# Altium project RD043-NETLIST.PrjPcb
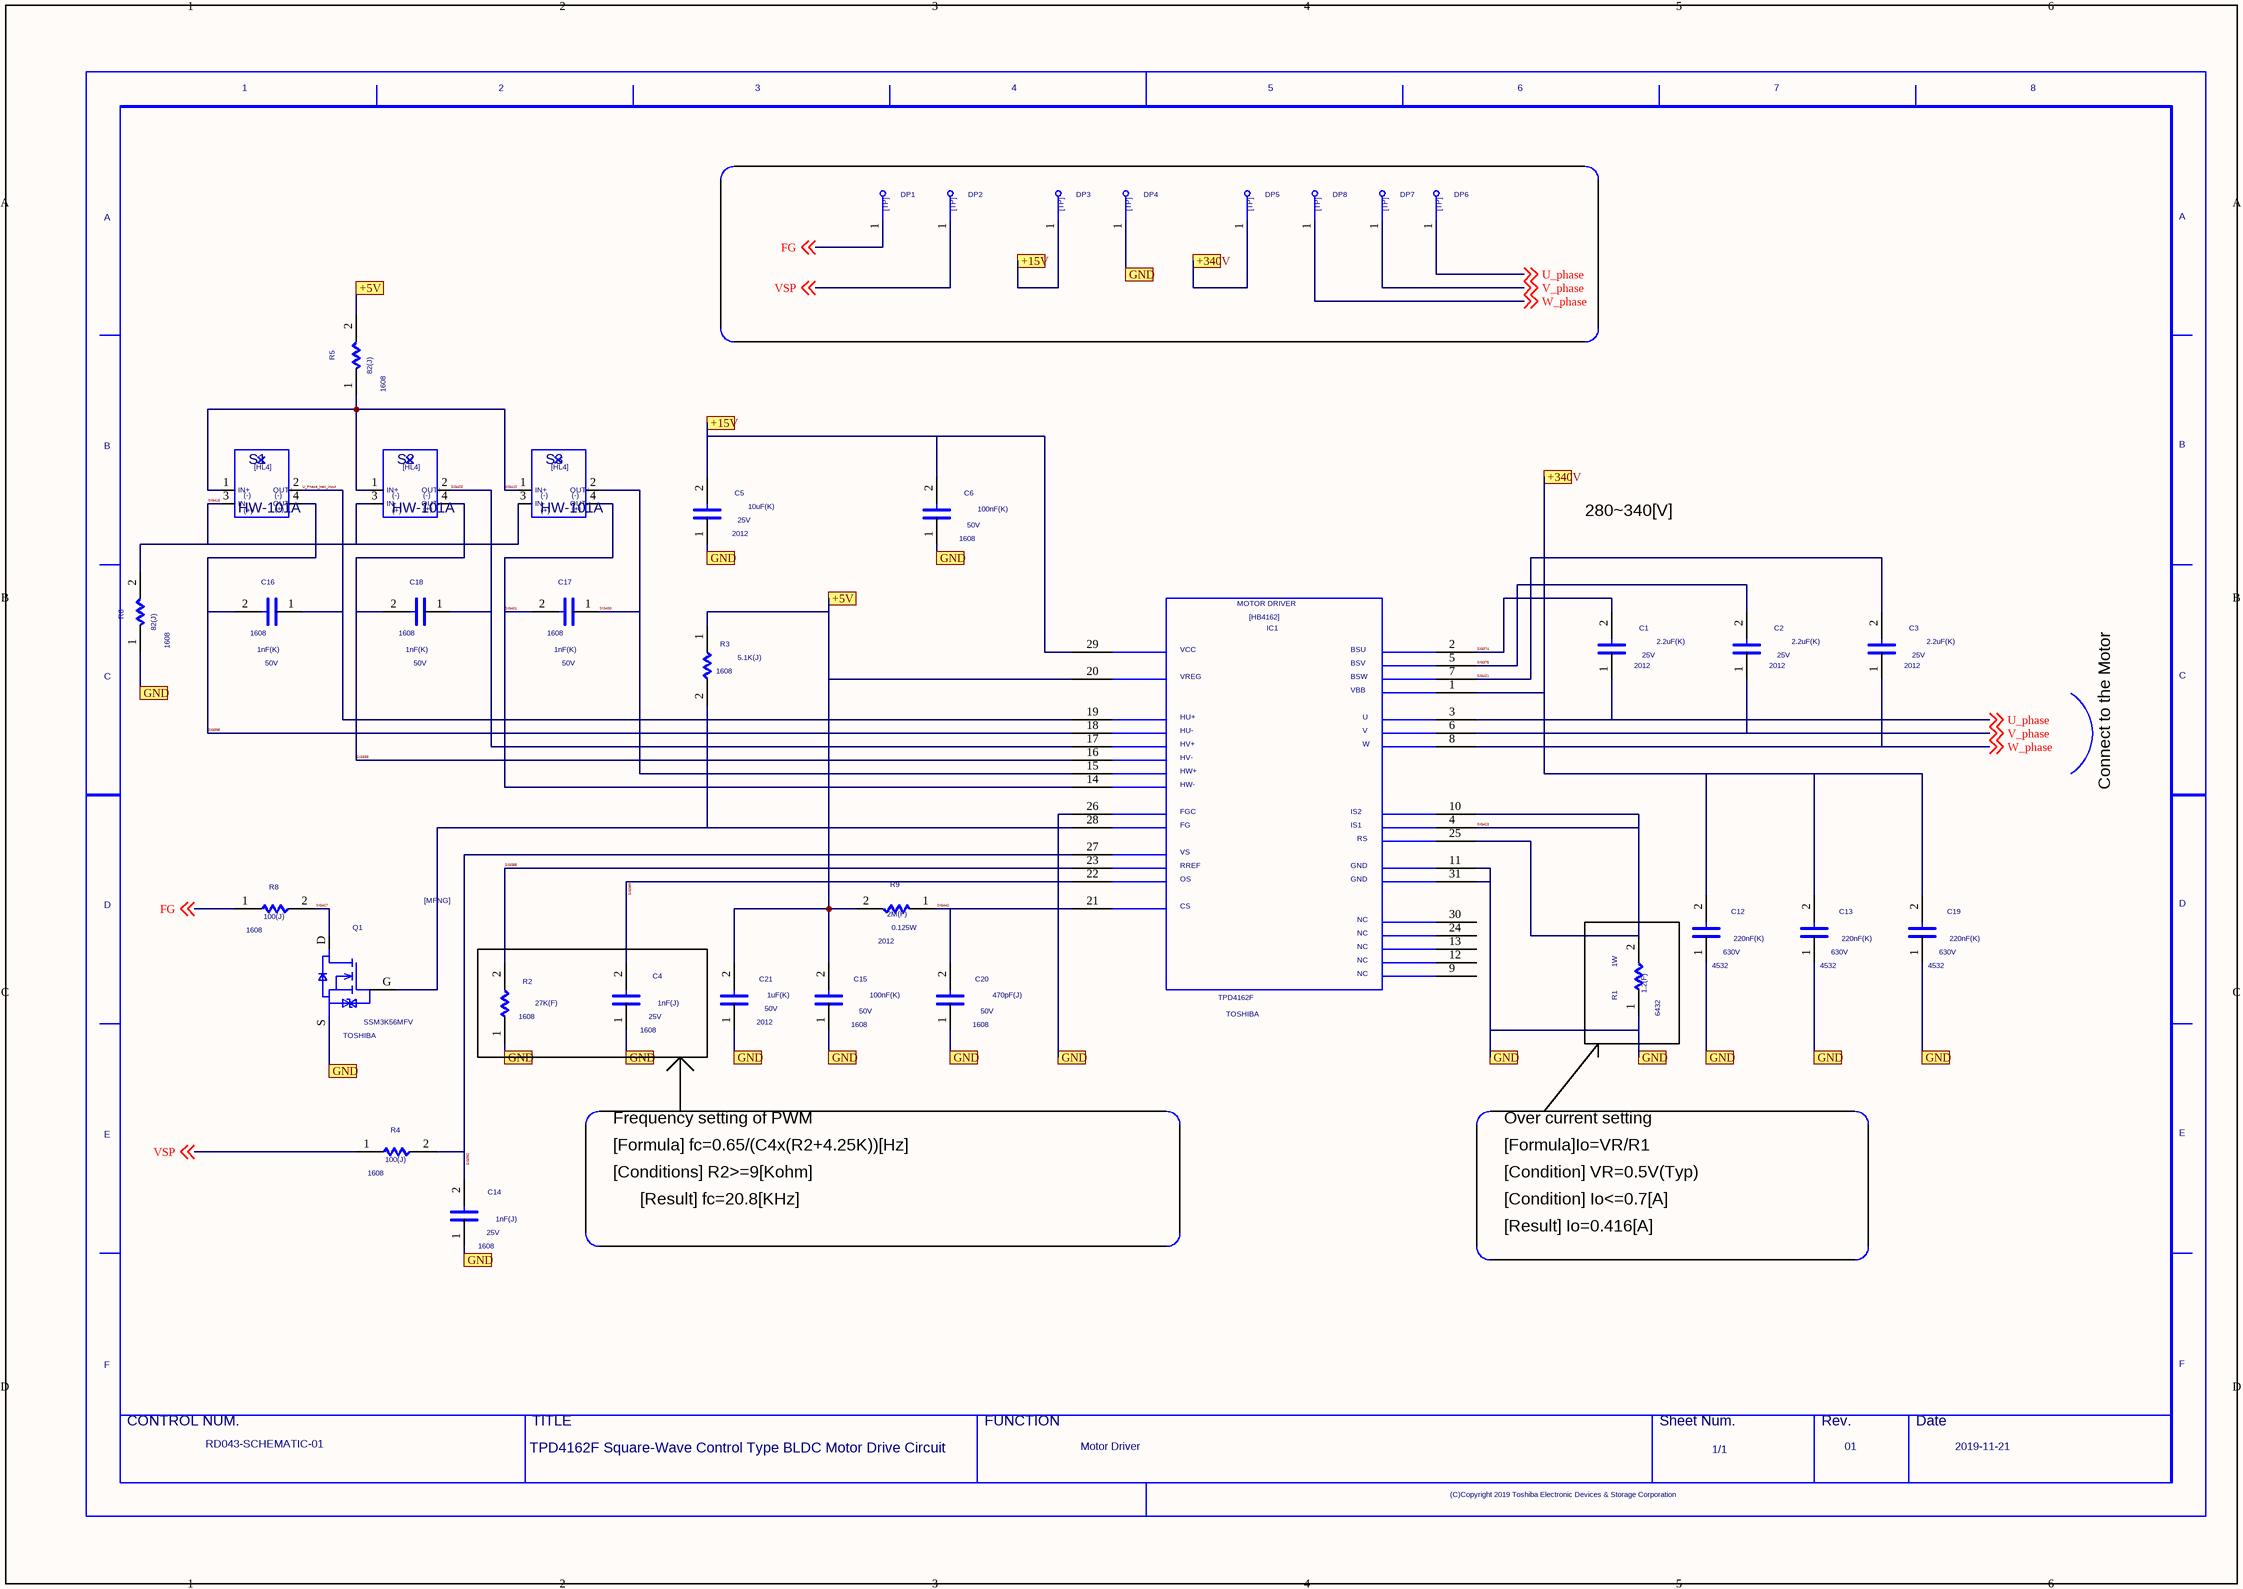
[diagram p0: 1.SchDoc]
1 sheet, 38 parts. Net scope: flat (ports and power ports of the same name join across sheets).

## Sheet 1.SchDoc
size 420 x 297 mm

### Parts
C1  SIZECODESMD: 2012  VAL2: 25V  VAL1: 2.2uF(K)  (hidden comment: C)
C2  SIZECODESMD: 2012  VAL2: 25V  VAL1: 2.2uF(K)  (hidden comment: C)
C3  SIZECODESMD: 2012  VAL2: 25V  VAL1: 2.2uF(K)  (hidden comment: C)
C4  SIZECODESMD: 1608  VAL2: 25V  VAL1: 1nF(J)  (hidden comment: C)
C5  SIZECODESMD: 2012  VAL2: 25V  VAL1: 10uF(K)  (hidden comment: C)
C6  SIZECODESMD: 1608  VAL2: 50V  VAL1: 100nF(K)  (hidden comment: C)
C12  SIZECODESMD: 4532  VAL2: 630V  VAL1: 220nF(K)  (hidden comment: C)
C13  SIZECODESMD: 4532  VAL2: 630V  VAL1: 220nF(K)  (hidden comment: C)
C14  SIZECODESMD: 1608  VAL2: 25V  VAL1: 1nF(J)  (hidden comment: C)
C15  SIZECODESMD: 1608  VAL2: 50V  VAL1: 100nF(K)  (hidden comment: C)
C16  SIZECODESMD: 1608  VAL2: 50V  VAL1: 1nF(K)  (hidden comment: C)
C17  SIZECODESMD: 1608  VAL2: 50V  VAL1: 1nF(K)  (hidden comment: C)
C18  SIZECODESMD: 1608  VAL2: 50V  VAL1: 1nF(K)  (hidden comment: C)
C19  SIZECODESMD: 4532  VAL2: 630V  VAL1: 220nF(K)  (hidden comment: C)
C20  SIZECODESMD: 1608  VAL2: 50V  VAL1: 470pF(J)  (hidden comment: C)
C21  SIZECODESMD: 2012  VAL2: 50V  VAL1: 1uF(K)  (hidden comment: C)
DP1  TP  (value not drawn)
DP2  TP  (value not drawn)
DP3  TP  (value not drawn)
DP4  TP  (value not drawn)
DP5  TP  (value not drawn)
DP6  TP  (value not drawn)
DP7  TP  (value not drawn)
DP8  TP  (value not drawn)
IC1  USERCOMPTEXT3: TOSHIBA  VAL3: TPD4162F  (hidden comment: HB4162)
Q1  USERCOMPTEXT1: TOSHIBA  VAL1: SSM3K56MFV  (hidden comment: MFNG)
R1  SIZECODESMD: 6432  VAL2: 1W  VAL1: 1.2(F)  (hidden comment: R)
R2  SIZECODESMD: 1608  VAL1: 27K(F)  (hidden comment: R)
R3  SIZECODESMD: 1608  VAL1: 5.1K(J)  (hidden comment: R)
R4  SIZECODESMD: 1608  VAL1: 100(J)  (hidden comment: R)
R5  SIZECODESMD: 1608  VAL1: 82(J)  (hidden comment: R)
R6  SIZECODESMD: 1608  VAL1: 82(J)  (hidden comment: R)
R8  SIZECODESMD: 1608  VAL1: 100(J)  (hidden comment: R)
R9  SIZECODESMD: 2012  VAL2: 0.125W  VAL1: 2M(F)  (hidden comment: R)
S1  VAL3: HW-101A  (hidden comment: HL4)
S2  VAL3: HW-101A  (hidden comment: HL4)
S3  VAL3: HW-101A  (hidden comment: HL4)
U?  DATE: 2019-11-21  TITLE: TPD4162F Square-Wave Control Type / BLDC Motor Drive Circuit  REVISION: 01  SHEETNUMBER: 1/1  DRAWINGNUMBER: RD043-SCHEMATIC-01  FUNCTION: Motor Driver  (hidden comment: WAKU_DEF100)

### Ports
+5V, +15V, +340V, GND

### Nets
FG: DP1.1 R8.1 ; off-sheet FG
Rotation_information: IC1.28 Q1.G R3.2
SIG374: C1.2 IC1.2
SIG375: C2.2 IC1.5
SIG388: IC1.23 R2.2
SIG389: C4.2 IC1.22
SIG392: C14.2 IC1.27 R4.2
SIG398: C16.2 IC1.18 S1.4
SIG399: C18.2 IC1.16 S2.4
SIG400: C17.1 IC1.15 S3.2
SIG401: C17.2 IC1.14 S3.4
SIG402: C18.1 IC1.17 S2.2
SIG410: R5.1 S1.1 S2.1 S3.1
SIG415: R6.2 S1.3 S2.3 S3.3
SIG421: C3.2 IC1.7
SIG423: IC1.4 IC1.10 IC1.25 R1.2
SIG427: Q1.D R8.2
SIG440: C20.2 IC1.21 R9.1
U_phase: C1.1 DP6.1 IC1.3 ; off-sheet U_phase
U_Phase_Hall_Input: C16.1 IC1.19 S1.2
V_phase: C2.1 DP7.1 IC1.6 ; off-sheet V_phase
VSP: DP2.1 R4.1 ; off-sheet VSP
W_phase: C3.1 DP8.1 IC1.8 ; off-sheet W_phase
NetC4_1: C4.1 C5.1 C6.1 C12.1 C13.1 C14.1 C15.1 C19.1 C20.1 C21.1 DP4.1 IC1.11 IC1.26 IC1.31 Q1.S R1.1 R2.1 R6.1 ; port GND
NetC5_2: C5.2 C6.2 DP3.1 IC1.29 ; port +15V
NetC12_2: C12.2 C13.2 C19.2 DP5.1 IC1.1 ; port +340V
NetC15_2: C15.2 C21.2 IC1.20 R3.1 R5.2 R9.2 ; port +5V

Not connected (* = marked no-connect by the designer): IC1 9 12 13 24 30

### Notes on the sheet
- 280~340[V]
- Connect to the Motor
- Frequency setting of PWM
- Over current setting
- [Formula] fc=0.65/(C4x(R2+4.25K))[Hz]
- [Conditions] R2>=9[Kohm]
- [Result] fc=20.8[KHz]
- [Formula]Io=VR/R1
- [Condition] VR=0.5V(Typ)
- [Condition] Io<=0.7[A]
- [Result] Io=0.416[A]

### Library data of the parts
C1-C3 = C: PARTNAME: GDM030002425; OriginalSymbolOrigin: (2540,7620); VAL3: GRM219B31E225KA75D; COMPONENTNAME: GDM030002425_package; MAXGCOUNT: 1
C4 C14 = C: PARTNAME: PRT_3; OriginalSymbolOrigin: (2540,7620); TEMPCHARACTERI2: CH; RATEDVOLTAGE: 25; MAXGCOUNT: 1; OUMEMAKER: MRT 村田製作所; QUADMODEL: CON_1N; FNLEADFREETHET1GT2GMCTH1: N_N_N; OUMECLASSIFICATION: セラミックコンデンサ; NOMINALCAPACITA: 1n; OUMEMAKERKATAMEI: GRM1882C1E102JA01D; CAPACITANCETOLE: J; CDMASTERCADCELG: C8100E; ADSMODELNAME: s_GRM1882C1E102JA01D
C5 = C: PARTNAME: K0302660; OriginalSymbolOrigin: (2540,7620); VAL3: TMK212BBJ106KG-T; COMPONENTNAME: K0302660_package; MAXGCOUNT: 1
C6 C15 = C: PARTNAME: GDM030001707; OriginalSymbolOrigin: (2540,7620); VAL3: GCM188R71H104KA57D; COMPCOMMENT: 代替：C1608JB1H104K; COMPONENTNAME: GDM030001707_package; MAXGCOUNT: 1
C12 C13 C19 = C: PARTNAME: PRT_6; OriginalSymbolOrigin: (2540,7620); MAXGCOUNT: 1; TEMPCHARACTERI2: B; RATEDVOLTAGE: 250; CAPACITANCETOLE: K; NOMINALCAPACITA: 150n; FNLEADFREETHET1GT2GMCTH1: N_N_N; CDMASTERCADCELG: DC835R; OUMEMAKER: TDK ＴＤＫ; OUMEMAKERKATAMEI: C4532JB2E154KT_EMBEDED; OUMECLASSIFICATION: セラミックコンデンサ; ADSMODELNAME: s_C4532JB2E154KT_EMBEDED; QUADMODEL: CON_150N
C16-C18 = C: PARTNAME: GDM030001796; OriginalSymbolOrigin: (2540,7620); VAL3: CM105B102K50AT; COMPONENTNAME: GDM030001796_package; MAXGCOUNT: 1
C20 = C: PARTNAME: GDM030001728; OriginalSymbolOrigin: (2540,7620); VAL3: GCM1885C1H471JA16D; MAXGCOUNT: 1; COMPONENTNAME: GDM030001728_package
C21 = C: PARTNAME: GDM030002107; OriginalSymbolOrigin: (2540,7620); VAL3: GRM21BB31H105KA12L; COMPONENTNAME: GDM030002107_package; MAXGCOUNT: 1
DP1-DP8 = TP: PARTNAME: ZS_DTP805; TIME: 16:12:21; UPDATEUSER: fukuda-y; UPDATETIME: 16:18:11; SAVECOUNT: 2; SAVEAREA0: -242,-92,12810,7836; OriginalSymbolOrigin: (0,7620); COMPONENTNAME: ZS_DTP805_package; MAXGCOUNT: 1
IC1 = HB4162: PARTNAME: K48S0004; OUMEPARTTYPE: IC; SAVEAREA0: -82747,-21522,160014,99323; TIME: 17:23:26; UPDATEUSER: w90028dm; UPDATETIME: 09:08:57; SAVECOUNT: 14; OriginalSymbolOrigin: (7620,76200); COMPONENTNAME: K48S0004_package; MAXGCOUNT: 1
Q1 = MFNG: PARTNAME: K4101030; OUMEPARTTYPE: Q; SAVECOUNT: 17; SAVEAREA0: -7084,-293,21840,15991; OriginalSymbolOrigin: (5080,12700); COMPONENTNAME: K4101030_package; MAXGCOUNT: 1
R1 = R: SQ_PART_MODEL: RES_1K; PARTNAME: PRT_5; OriginalSymbolOrigin: (5080,5080); MAXGCOUNT: 1; RESISTANCETOLER: J; NOMINALRESISTAN: 1K; FNLEADFREETHET1GT2GMCTH1: 3_1_N; CDMASTERCADCELG: R8100A; OUMECLASSIFICATION: 表面実装用固定抵抗器; ADSCNVFLAG: ON
R2 = R: PARTNAME: PRT_2; OriginalSymbolOrigin: (5080,5080); MAXGCOUNT: 1; OUMEMAKER: NAE パナソニックエレクトロニックデバイス; QUADMODEL: RES_27K; MOUNTINGFORMSMD: SMD; FNLEADFREETHET1GT2GMCTH1: N_N_N; OUMECLASSIFICATION: 表面実装用固定抵抗器; RESISTANCETOLER: F; POWERRATING: 100m; OUMEMAKERKATAMEI: ERJ3EKF2702V; NOMINALRESISTAN: 27K; VAL2: 100mW; CDMASTERCADCELG: KC0008; ADSMODELNAME: s_ERJ3EKF2702V
R3 = R: PARTNAME: GDM010001091; OriginalSymbolOrigin: (5080,5080); VAL3: ERJ3GEYJ512V; COMPONENTNAME: GDM010001091_package; MAXGCOUNT: 1; VAL2: 63mW
R4 = R: PARTNAME: K0102020; OriginalSymbolOrigin: (5080,5080); COMPONENTNAME: K0102020_package; MAXGCOUNT: 1; VAL2: 100mW
R5 R6 = R: PARTNAME: PRT_1; OriginalSymbolOrigin: (5080,5080); MAXGCOUNT: 1; OUMEMAKER: NAE パナソニックエレクトロニックデバイス; QUADMODEL: RES_330; MOUNTINGFORMSMD: SMD; FNLEADFREETHET1GT2GMCTH1: 3_1_N; OUMECLASSIFICATION: 表面実装用固定抵抗器; RESISTANCETOLER: J; POWERRATING: 63m; OUMEMAKERKATAMEI: ERJ3GEYJ331V; NOMINALRESISTAN: 330; VAL2: 100mW; CDMASTERCADCELG: KC0008; ADSMODELNAME: s_ERJ3GEYJ331V
R8 = R: OriginalSymbolOrigin: (5080,5080); COMPONENTNAME: K0102020_package; FUNCTION: K0102020; MAXGCOUNT: 1; VAL2: 100mW
R9 = R: ICX_PART_MODEL: RES_2M; PARTNAME: PRT_4; OriginalSymbolOrigin: (5080,5080); MAXGCOUNT: 1; MOUNTINGFORMSMD: SMD; POWERRATING: 100m; RESISTANCETOLER: J; NOMINALRESISTAN: 2M; FNLEADFREETHET1GT2GMCTH1: 3_1_N; CDMASTERCADCELG: DR910A; OUMEMAKER: NAE パナソニックエレクトロニックデバイス; OUMEMAKERKATAMEI: ERJ6GEYJ205V; OUMECLASSIFICATION: 表面実装用固定抵抗器; ADSMODELNAME: s_ERJ6GEYJ205V; ADSCOMPONENTNAME: R_2012
S1 S2 = HL4: PARTNAME: K49S0002; OUMEPARTTYPE: MT; TIME: 12:13:08; UPDATEUSER: e1023210; UPDATETIME: 16:10:58; SAVECOUNT: 25; SAVEAREA0: -742,-353,31311,30816; OriginalSymbolOrigin: (2540,13970); GraphTrnsfNameProp: HL4_X0.50_Y0.50; COMPONENTNAME: K49S0002_package; MAXGCOUNT: 1
S3 = HL4: PARTNAME: K49S0002; OUMEPARTTYPE: MT; TIME: 12:13:08; UPDATEUSER: e1023210; UPDATETIME: 16:10:58; SAVECOUNT: 25; SAVEAREA0: -742,-353,31311,30816; OriginalSymbolOrigin: (2540,13970); GraphTrnsfNameProp: HL4_X0.50_Y0.50; NOTMOUNT: MOUNT; COMPONENTNAME: K49S0002_package; MAXGCOUNT: 1
U? = WAKU_DEF100: PLOTTIME: HH:MM; SAVEAREA0: -63393,-16950,474261,314592; TIME: 14:30:25; UPDATEUSER: t5459927; UPDATETIME: 13:36:51; SAVECOUNT: 4; OriginalSymbolOrigin: (10160,284480)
